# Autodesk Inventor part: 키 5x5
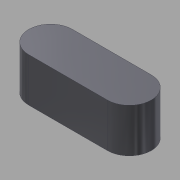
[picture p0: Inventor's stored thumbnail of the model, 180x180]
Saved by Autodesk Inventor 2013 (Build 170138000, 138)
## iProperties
Created: 2014-10
Part Number: 키 5x5
Document SubType Name: Modeling
Designer: KYOUNG IL JANG
Density: 7.86 g/cm^3
Mass: 2.54015 g
Surface Area: 2.9781 cm^2
Volume: 0.323175 cm^3
Material: 강철, 연강
Author: SeoGD™ [www.esajin.kr]
Revision Number: 1
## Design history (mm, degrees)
sketch "스케치1"
  geometry: L1 (-4.5, -2.5)-(4.5, -2.5); L2 (4.5, 2.5)-(-4.5, 2.5); A1 r 2.5 centre (4.5, 0) between (4.5, -2.5) and (4.5, 2.5); A2 r 2.5 centre (-4.5, 0) between (-4.5, 2.5) and (-4.5, -2.5); 2 further points
  constraints: 4 end point, 4 point on circle, 4 tangent, 2 centre point, 1 horizontal, 1 horizontal alignment, 1 midpoint, 1 parallel, 1 vertical alignment
  dimensions: "d0" = 5 distance between parallel lines of L1 L2; "d1" = 14 dimension on A1 A2
extrude "돌출1" new body sketch "스케치1" stored distance "d2" = 5; taper "d3" = 0 deg
node "솔리드1"
